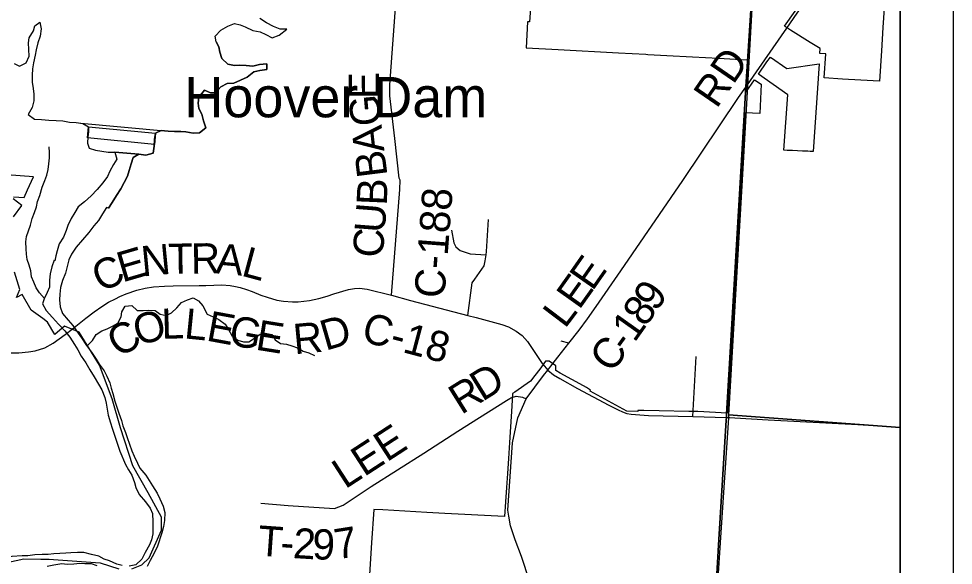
# Model space of a CAD drawing. Extents: x 0 to 34, y 0 to 22.
# Drawn here: x 7.246 to 9, y 18.938 to 19.964 of the extents above; entities that cross this region are included whole.
import ezdxf

# ---------------------------------------------------------------- set-up
doc = ezdxf.new("R2010")
doc.units = 0
for name, color, linetype in [('Default', 7, 'Continuous'), ('GM_X_Corporation', 7, 'Continuous'), ('GM_X_County_Road', 7, 'Continuous'), ('GM_X_County_Road_Text', 7, 'Continuous'), ('GM_X_Hydro', 7, 'Continuous'), ('GM_X_Hydro_Text', 7, 'Continuous'), ('GM_X_Major_Lake', 7, 'Continuous'), ('GM_X_Major_River', 7, 'Continuous'), ('GM_X_Minor_River', 7, 'Continuous'), ('GM_X_Township_Road', 7, 'Continuous'), ('GM_X_Township_Road_Text', 7, 'Continuous'), ('SH_Data', 7, 'Continuous')]:
    doc.layers.add(name, color=color, linetype=linetype)

msp = doc.modelspace()

# ---------------------------------------------------------------- linework, layer by layer
at = {"layer": 'Default'}
for points in [[(8.9, 19.1966), (8.9, 20.2132), (8.6374, 20.2329), (8.6338, 20.179), (8.6233, 20.0051), (8.6057, 19.6933), (8.5782, 19.2201)], [(8.9, 18.6616), (8.9, 19.1966), (8.5782, 19.2201), (8.5779, 19.2144), (8.5637, 18.9993), (8.5431, 18.6841)]]:
    msp.add_lwpolyline(points, close=True, dxfattribs=at)
at = {"layer": 'GM_X_Corporation'}
for points in [[(8.9, 16.0691), (8.9, 20.2026)], [(8.2101, 20.0366), (8.2048, 19.9577), (8.2009, 19.9579), (8.1985, 19.9091), (8.2581, 19.9059), (8.3717, 19.8996), (8.423, 19.8968), (8.4268, 19.8966), (8.4622, 19.8946), (8.5104, 19.892), (8.5591, 19.8893), (8.6016, 19.8869), (8.6149, 19.8862), (8.6149, 19.8862), (8.6149, 19.8862), (8.6126, 19.8519), (8.6124, 19.8478), (8.6114, 19.8265), (8.6271, 19.8492), (8.6394, 19.8405), (8.6369, 19.786), (8.6093, 19.787), (8.607, 19.7425), (8.6058, 19.7195), (8.6055, 19.7139), (8.6047, 19.7018), (8.6042, 19.6931), (8.6031, 19.6746), (8.6026, 19.6668), (8.6022, 19.6605), (8.6017, 19.651), (8.6011, 19.642), (8.6005, 19.6321), (8.5999, 19.6227), (8.5994, 19.6132), (8.5987, 19.6028), (8.5981, 19.593), (8.5976, 19.5835), (8.5968, 19.571), (8.5959, 19.5552), (8.5954, 19.548), (8.5946, 19.5342), (8.5944, 19.5318), (8.594, 19.5248), (8.5934, 19.5153), (8.5929, 19.5059), (8.5923, 19.4964), (8.5917, 19.487), (8.5911, 19.4775), (8.5906, 19.4679), (8.59, 19.4586), (8.5894, 19.4492), (8.5888, 19.4386), (8.5881, 19.428), (8.5872, 19.4125), (8.5868, 19.406), (8.5858, 19.3894), (8.5852, 19.38), (8.5846, 19.3701), (8.5841, 19.3607), (8.5835, 19.3512), (8.5829, 19.3408), (8.5823, 19.3319), (8.5817, 19.3225), (8.5811, 19.3127), (8.5806, 19.3032), (8.58, 19.2934), (8.5794, 19.2839), (8.5792, 19.2811), (8.5788, 19.2741), (8.5782, 19.2646), (8.5775, 19.2526), (8.5759, 19.2262), (8.5758, 19.2236), (8.5203, 19.2263), (8.5035, 19.2266), (8.4477, 19.2277), (8.4193, 19.2283), (8.4079, 19.2285), (8.4078, 19.2268), (8.3875, 19.2271), (8.3183, 19.2647), (8.3192, 19.2663), (8.3113, 19.2717), (8.306, 19.2745), (8.2623, 19.2982), (8.2541, 19.3033), (8.2542, 19.3125), (8.2412, 19.3208), (8.2347, 19.3207), (8.2241, 19.3061), (8.2147, 19.2942), (8.2064, 19.2836), (8.1769, 19.2631), (8.1723, 19.26), (8.1716, 19.2365), (8.1691, 19.198), (8.1671, 19.1683), (8.1651, 19.1386), (8.1633, 19.1102), (8.1615, 19.0836), (8.1597, 19.0568), (8.1579, 19.0296), (8.0457, 19.0349), (8.0118, 19.0369), (7.9291, 19.0419), (7.9121, 19.0429), (7.908, 18.98), (7.9029, 18.9004)], [(8.8726, 20.0212), (8.8678, 19.9474), (8.865, 19.9032), (8.8613, 19.8462), (8.8267, 19.8483), (8.7921, 19.8504), (8.7577, 19.8525), (8.7605, 19.8979), (8.7496, 19.8985), (8.7502, 19.9075), (8.7315, 19.9191), (8.6942, 19.9423), (8.6926, 19.9434), (8.683, 19.9494), (8.7229, 20.0068)], [(7.2358, 19.6296), (7.2557, 19.6283), (7.2624, 19.6426), (7.2737, 19.6668), (7.1807, 19.674)], [(7.2359, 19.5917), (7.2516, 19.6128), (7.2356, 19.6258)], [(7.4582, 18.9315), (7.4768, 18.9386), (7.4904, 18.952), (7.514, 19.0041), (7.5139, 19.0283), (7.4886, 19.0736), (7.4602, 19.1244), (7.437, 19.1957), (7.4213, 19.2503), (7.3975, 19.3136), (7.3591, 19.3754), (7.3315, 19.3868), (7.3137, 19.3711), (7.2996, 19.3944), (7.2912, 19.4013), (7.2689, 19.4166), (7.2521, 19.4458), (7.2416, 19.4406), (7.248, 19.4555), (7.238, 19.4882)], [(7.1741, 18.9115), (7.2181, 18.9421), (7.2552, 18.9501), (7.2874, 18.9493), (7.2953, 18.9495), (7.3032, 18.9493), (7.3111, 18.9486), (7.3984, 18.9427), (7.4334, 18.9313)]]:
    msp.add_lwpolyline(points, dxfattribs=at)
msp.add_lwpolyline([(8.7074, 19.7156), (8.6979, 19.716), (8.6884, 19.7163), (8.6822, 19.7166), (8.6891, 19.8208), (8.6344, 19.8597), (8.6503, 19.8825), (8.6567, 19.8917), (8.6874, 19.8703), (8.7484, 19.8791), (8.737, 19.7145), (8.7315, 19.7147), (8.7267, 19.7149), (8.7168, 19.7153)], close=True, dxfattribs=at)
at = {"layer": 'GM_X_County_Road'}
for p, q in [((8.6305, 19.8639), (8.6874, 19.9459)), ((8.6134, 19.8393), (8.6305, 19.8639)), ((8.2324, 19.3115), (8.2388, 19.3039)), ((8.2388, 19.3039), (8.2445, 19.3113))]:
    msp.add_line(p, q, dxfattribs=at)
for points in [[(8.4511, 17.1951), (8.4574, 17.2984), (8.4834, 17.726), (8.4924, 17.8634), (8.4933, 17.8764), (8.5463, 18.6832), (8.5517, 18.8459), (8.5602, 18.986), (8.5739, 19.2101), (8.5742, 19.2159), (8.5745, 19.2215), (8.6104, 19.8358), (8.636, 20.2294), (8.6772, 20.9), (3.9336, 20.9)], [(7.9453, 19.445), (7.9609, 19.6428), (7.9617, 19.6607), (7.9601, 19.6645), (7.9516, 19.7386), (7.9426, 19.8187), (7.9422, 19.8278), (7.9426, 19.8396), (7.9547, 20.0094), (7.9614, 20.1033), (7.9665, 20.1933), (7.9716, 20.2761), (7.9801, 20.3643), (7.9832, 20.4168)], [(8.6874, 19.9459), (8.7068, 19.9738), (8.7395, 20.0202), (8.7885, 20.0901), (8.8301, 20.1469), (8.8468, 20.1682), (8.8566, 20.1827), (8.8626, 20.203), (8.8633, 20.2102)], [(8.2445, 19.3113), (8.2576, 19.3282), (8.2782, 19.3547), (8.2977, 19.3793), (8.3136, 19.4005), (8.3296, 19.4234), (8.3762, 19.4905), (8.4924, 19.6602), (8.5968, 19.8155), (8.6106, 19.8352), (8.6134, 19.8393)], [(7.3532, 19.3866), (7.372, 19.4015), (7.3875, 19.4133), (7.4017, 19.4233), (7.4144, 19.4314), (7.4274, 19.4382), (7.4358, 19.4424), (7.4473, 19.4472), (7.4672, 19.4542), (7.4831, 19.458), (7.499, 19.4607), (7.5196, 19.4619), (7.5359, 19.4625), (7.5842, 19.4631)], [(7.5842, 19.4631), (7.5973, 19.4632), (7.6273, 19.464), (7.6424, 19.4629), (7.6528, 19.4613), (7.6617, 19.459), (7.6736, 19.4555), (7.6842, 19.4516), (7.7005, 19.4451), (7.7119, 19.4408), (7.73, 19.4355), (7.7429, 19.4335), (7.7596, 19.4323), (7.7706, 19.4322), (7.781, 19.4334), (7.7914, 19.4349), (7.8093, 19.4386), (7.8245, 19.4432), (7.8373, 19.4474), (7.8645, 19.4552), (7.8759, 19.4571), (7.8853, 19.4577), (7.9001, 19.4562), (7.9453, 19.445), (7.9813, 19.4346), (8.0886, 19.4067), (8.1043, 19.4027), (8.1526, 19.3897), (8.1653, 19.3851), (8.1797, 19.3774), (8.1907, 19.3691), (8.2009, 19.3576), (8.228, 19.3168), (8.2324, 19.3115)], [(7.0874, 19.347), (7.1621, 19.3409), (7.2264, 19.3363), (7.2457, 19.3363), (7.2644, 19.3382), (7.2765, 19.3403), (7.2946, 19.3457), (7.3106, 19.3545), (7.3332, 19.3707), (7.3462, 19.381), (7.3532, 19.3866)], [(8.1656, 19.03), (8.1636, 19.0412), (8.1727, 19.1677), (8.1825, 19.2149), (8.1981, 19.2503), (8.2308, 19.2941), (8.2388, 19.3039)], [(8.2388, 19.3039), (8.2498, 19.2952), (8.2614, 19.2882), (8.2949, 19.2697), (8.3532, 19.2383), (8.3711, 19.2297), (8.3791, 19.226), (8.3872, 19.2228), (8.3952, 19.2212), (8.4276, 19.2187), (8.5112, 19.2172), (8.5744, 19.2154), (8.5806, 19.2151)], [(8.5806, 19.2151), (8.5899, 19.2146), (8.6527, 19.2111), (8.8207, 19.2019), (8.9, 19.1974)], [(8.251, 18.3328), (8.267, 18.5617), (8.2747, 18.6747), (8.2755, 18.6956), (8.2751, 18.6998), (8.2717, 18.7125), (8.2411, 18.7994), (8.2194, 18.8631), (8.1895, 18.9547), (8.1777, 18.9855), (8.1688, 19.0118), (8.1656, 19.03)]]:
    msp.add_lwpolyline(points, dxfattribs=at)
msp.add_lwpolyline([(8.9, 16.069), (8.9, 20.9), (8.6772, 20.9), (8.636, 20.2294), (8.6104, 19.8358), (8.5745, 19.2215), (8.5742, 19.2159), (8.5739, 19.2101), (8.5602, 18.986), (8.5517, 18.8459), (8.5463, 18.6832), (8.4933, 17.8764), (8.4924, 17.8634), (8.4834, 17.726), (8.4574, 17.2984), (8.4511, 17.1951), (8.4246, 16.7343), (8.4151, 16.5575), (8.4046, 16.4383), (8.3992, 16.2979), (8.3884, 16.1033), (8.4715, 16.0965), (8.5217, 16.0919)], close=True, dxfattribs=at)
at = {"layer": 'GM_X_Hydro'}
msp.add_lwpolyline([(7.3749, 19.7402), (7.3769, 19.7609), (7.5028, 19.7486), (7.5008, 19.7278)], close=True, dxfattribs=at)
at = {"layer": 'GM_X_Major_Lake'}
for p, q in [((7.3621, 19.7673), (7.5193, 19.7531)), ((7.426, 19.7132), (7.4715, 19.7092))]:
    msp.add_line(p, q, dxfattribs=at)
for points in [[(7.6167, 19.9204), (7.6148, 19.931), (7.6251, 19.942), (7.6381, 19.9499), (7.651, 19.9544), (7.6612, 19.9521), (7.6711, 19.9483), (7.6851, 19.9417), (7.6987, 19.939), (7.7093, 19.9337), (7.7214, 19.9279), (7.7347, 19.9324), (7.7488, 19.9437), (7.7363, 19.9442), (7.7238, 19.9488), (7.7109, 19.9557), (7.6985, 19.9637)], [(7.2474, 19.8743), (7.2599, 19.8807), (7.2653, 19.8935), (7.2646, 19.9057), (7.2643, 19.9182), (7.2655, 19.9277), (7.2735, 19.941), (7.2762, 19.9504), (7.2857, 19.9569), (7.2879, 19.9447), (7.286, 19.9307), (7.2814, 19.9185), (7.2786, 19.9049), (7.2767, 19.895), (7.2736, 19.8806), (7.2716, 19.8696), (7.2708, 19.8578), (7.2708, 19.8442), (7.273, 19.8324), (7.2744, 19.8218), (7.2744, 19.8096), (7.2713, 19.7967), (7.2636, 19.7838), (7.2757, 19.775), (7.2886, 19.7742), (7.3023, 19.773), (7.3159, 19.7726), (7.3288, 19.7718), (7.341, 19.7694), (7.3538, 19.7686), (7.3621, 19.7673)], [(7.2474, 19.8743), (7.2599, 19.8807), (7.2653, 19.8935), (7.2646, 19.9057), (7.2643, 19.9182), (7.2655, 19.9277), (7.2735, 19.941), (7.2762, 19.9504), (7.2857, 19.9569), (7.2879, 19.9447), (7.286, 19.9307), (7.2814, 19.9185), (7.2786, 19.9049), (7.2767, 19.895), (7.2736, 19.8806), (7.2716, 19.8696), (7.2708, 19.8578), (7.2708, 19.8442), (7.273, 19.8324), (7.2744, 19.8218), (7.2744, 19.8096), (7.2713, 19.7967), (7.2636, 19.7838), (7.2757, 19.775), (7.2886, 19.7742), (7.3023, 19.773), (7.3159, 19.7726), (7.3288, 19.7718), (7.341, 19.7694), (7.3538, 19.7686), (7.3663, 19.7667), (7.3769, 19.7609), (7.3765, 19.7514), (7.3757, 19.7419), (7.3749, 19.7302), (7.3783, 19.7207), (7.39, 19.7172), (7.4018, 19.7149), (7.4139, 19.7133), (7.426, 19.7132)], [(7.2474, 19.8743), (7.2599, 19.8807), (7.2653, 19.8935), (7.2646, 19.9057), (7.2643, 19.9182), (7.2655, 19.9277), (7.2735, 19.941), (7.2762, 19.9504), (7.2857, 19.9569), (7.2879, 19.9447), (7.286, 19.9307), (7.2814, 19.9185), (7.2786, 19.9049), (7.2767, 19.895), (7.2736, 19.8806), (7.2716, 19.8696), (7.2708, 19.8578), (7.2708, 19.8442), (7.273, 19.8324), (7.2744, 19.8218), (7.2744, 19.8096), (7.2713, 19.7967), (7.2636, 19.7838), (7.2757, 19.775), (7.2886, 19.7742), (7.3023, 19.773), (7.3159, 19.7726), (7.3288, 19.7718), (7.341, 19.7694), (7.3538, 19.7686), (7.3663, 19.7667), (7.3769, 19.7609), (7.3765, 19.7514), (7.3757, 19.7419), (7.3749, 19.7302), (7.3783, 19.7207), (7.39, 19.7172), (7.4018, 19.7149), (7.4139, 19.7133), (7.426, 19.7132)], [(7.4715, 19.7092), (7.4844, 19.7073), (7.4981, 19.7114), (7.5, 19.7247), (7.5005, 19.7372), (7.5028, 19.7486), (7.5131, 19.7538), (7.5263, 19.7523), (7.5381, 19.7518), (7.5499, 19.7518), (7.5597, 19.751), (7.573, 19.749), (7.5851, 19.7493), (7.5973, 19.7588), (7.5924, 19.7721), (7.5895, 19.7846), (7.5838, 19.7953), (7.5827, 19.8048), (7.5839, 19.8162), (7.5942, 19.8298), (7.6056, 19.8244), (7.6151, 19.8244), (7.6254, 19.8357), (7.6368, 19.8421), (7.6493, 19.8424), (7.6622, 19.8481), (7.6744, 19.8541), (7.687, 19.8639), (7.6984, 19.8661), (7.7116, 19.8683), (7.7113, 19.879), (7.698, 19.8779), (7.6855, 19.8745), (7.673, 19.8757), (7.6605, 19.8765), (7.6506, 19.8758), (7.6385, 19.8782), (7.6268, 19.8889), (7.6234, 19.901), (7.6212, 19.9109), (7.6167, 19.9204)], [(7.6167, 19.9204), (7.6212, 19.9109), (7.6234, 19.901), (7.6268, 19.8889), (7.6385, 19.8782), (7.6506, 19.8758), (7.6605, 19.8765), (7.673, 19.8757), (7.6855, 19.8745), (7.698, 19.8779), (7.7113, 19.879), (7.7116, 19.8683), (7.6984, 19.8661), (7.687, 19.8639), (7.6744, 19.8541), (7.6622, 19.8481), (7.6493, 19.8424), (7.6368, 19.8421), (7.6254, 19.8357), (7.6151, 19.8244), (7.6056, 19.8244), (7.5942, 19.8298), (7.5839, 19.8162), (7.5827, 19.8048), (7.5838, 19.7953), (7.5895, 19.7846), (7.5924, 19.7721), (7.5973, 19.7588), (7.5851, 19.7493), (7.573, 19.749), (7.5597, 19.751), (7.5499, 19.7518), (7.5381, 19.7518), (7.5263, 19.7523), (7.5131, 19.7538), (7.5028, 19.7486), (7.5005, 19.7372), (7.5, 19.7247), (7.4981, 19.7114), (7.4844, 19.7073), (7.4715, 19.7092)], [(7.5193, 19.7531), (7.5263, 19.7523), (7.5381, 19.7518), (7.5499, 19.7518), (7.5597, 19.751), (7.573, 19.749), (7.5851, 19.7493), (7.5973, 19.7588), (7.5924, 19.7721), (7.5895, 19.7846), (7.5838, 19.7953), (7.5827, 19.8048), (7.5839, 19.8162), (7.5942, 19.8298), (7.6056, 19.8244), (7.6151, 19.8244), (7.6254, 19.8357), (7.6368, 19.8421), (7.6493, 19.8424), (7.6622, 19.8481), (7.6744, 19.8541), (7.687, 19.8639), (7.6984, 19.8661), (7.7116, 19.8683), (7.7113, 19.879), (7.698, 19.8779), (7.6855, 19.8745), (7.673, 19.8757), (7.6605, 19.8765), (7.6506, 19.8758), (7.6385, 19.8782), (7.6268, 19.8889), (7.6234, 19.901), (7.6212, 19.9109), (7.6167, 19.9204)], [(7.2372, 19.8796), (7.2474, 19.8743)]]:
    msp.add_lwpolyline(points, dxfattribs=at)
at = {"layer": 'GM_X_Major_River'}
msp.add_line((7.4715, 19.7092), (7.426, 19.7132), dxfattribs=at)
for points in [[(7.426, 19.7132), (7.4297, 19.6999), (7.4236, 19.6897), (7.4167, 19.6776), (7.4125, 19.6677), (7.4037, 19.6553), (7.3931, 19.6432), (7.3816, 19.6311), (7.3694, 19.6197), (7.3576, 19.6103), (7.3511, 19.6001), (7.3442, 19.5887), (7.3381, 19.5755), (7.335, 19.566), (7.3297, 19.5539), (7.3216, 19.541), (7.3178, 19.5281), (7.3154, 19.5186), (7.3135, 19.5091)], [(7.426, 19.7132), (7.4297, 19.6999), (7.4236, 19.6897), (7.4167, 19.6776), (7.4125, 19.6677), (7.4037, 19.6553), (7.3931, 19.6432), (7.3816, 19.6311), (7.3694, 19.6197), (7.3576, 19.6103), (7.3511, 19.6001), (7.3442, 19.5887), (7.3381, 19.5755), (7.335, 19.566), (7.3297, 19.5539), (7.3216, 19.541), (7.3178, 19.5281), (7.3154, 19.5186), (7.3135, 19.5091)], [(7.4145, 19.6081), (7.4214, 19.6187), (7.4294, 19.632), (7.4374, 19.6441), (7.444, 19.6562), (7.4497, 19.668), (7.4532, 19.6789), (7.457, 19.6915), (7.4605, 19.7032), (7.4715, 19.7092)], [(7.4715, 19.7092), (7.4605, 19.7032), (7.457, 19.6915), (7.4532, 19.6789), (7.4497, 19.668), (7.444, 19.6562), (7.4374, 19.6441), (7.4294, 19.632), (7.4214, 19.6187), (7.4145, 19.6081)], [(7.4145, 19.6081), (7.4103, 19.6093), (7.4031, 19.5972), (7.3954, 19.5847), (7.3867, 19.5748), (7.3771, 19.5624), (7.3653, 19.5487), (7.3535, 19.5348), (7.3447, 19.5215), (7.3397, 19.5113), (7.337, 19.4988), (7.3335, 19.4859), (7.3281, 19.4726), (7.3239, 19.4593), (7.3227, 19.4464), (7.3223, 19.4358), (7.3233, 19.4229), (7.3282, 19.4104), (7.3388, 19.3982), (7.3474, 19.3882), (7.3542, 19.378), (7.3636, 19.365), (7.373, 19.3502), (7.3825, 19.338), (7.3911, 19.3246), (7.3968, 19.3151), (7.4062, 19.3026), (7.4111, 19.293), (7.4167, 19.2801), (7.4193, 19.2706), (7.4223, 19.2603), (7.4264, 19.2459), (7.4339, 19.2231), (7.4387, 19.2094), (7.4413, 19.1995), (7.4462, 19.1873), (7.4492, 19.1778), (7.4537, 19.1649), (7.4578, 19.1527), (7.4627, 19.1428), (7.4687, 19.1295), (7.4732, 19.12), (7.4841, 19.1071), (7.4909, 19.0972), (7.4969, 19.0873), (7.5056, 19.0735), (7.5108, 19.0629), (7.5168, 19.0488), (7.5202, 19.037), (7.5194, 19.0219), (7.5174, 19.0109), (7.5147, 18.9987), (7.5062, 18.9737), (7.5001, 18.9604), (7.4928, 18.9468), (7.4871, 18.9354)], [(7.3135, 19.5091), (7.3124, 19.5106), (7.3078, 19.4978), (7.305, 19.4849), (7.3035, 19.4727), (7.3034, 19.4598), (7.2992, 19.45), (7.2938, 19.4378), (7.2907, 19.4284), (7.2971, 19.4158), (7.3092, 19.4028), (7.3205, 19.3906), (7.3326, 19.3781), (7.342, 19.3659), (7.3503, 19.3525), (7.3567, 19.3423), (7.3631, 19.3305), (7.3717, 19.3179), (7.3793, 19.3046), (7.3875, 19.2916), (7.3954, 19.2775), (7.4015, 19.2669), (7.4075, 19.2528), (7.4097, 19.2422), (7.4119, 19.2308), (7.4137, 19.2198), (7.4182, 19.2053), (7.4212, 19.1954), (7.425, 19.184), (7.4283, 19.1745), (7.4317, 19.1635), (7.4354, 19.1521), (7.4459, 19.127), (7.4519, 19.1171), (7.4583, 19.1068), (7.4632, 19.0931), (7.4654, 19.0836), (7.4718, 19.071), (7.4839, 19.0573), (7.4926, 19.0451), (7.4967, 19.0349), (7.4974, 19.0197), (7.4972, 18.9969), (7.4953, 18.9855), (7.4915, 18.976), (7.4834, 18.9617), (7.4769, 18.9492), (7.4655, 18.939), (7.4533, 18.9364)], [(7.4401, 18.9376), (7.4302, 18.9399), (7.4162, 18.946), (7.4064, 18.9491), (7.3961, 18.9552), (7.3825, 18.9583), (7.3681, 18.9618), (7.3564, 18.9622), (7.3434, 18.9612), (7.334, 18.9604), (7.323, 18.9601), (7.3116, 18.9594), (7.3013, 18.9583), (7.29, 18.958), (7.2759, 18.9573), (7.2626, 18.9555), (7.2524, 18.9555), (7.2327, 18.9541), (7.2209, 18.9515), (7.2083, 18.9466), (7.1946, 18.936)], [(7.393, 18.9366), (7.3824, 18.9405), (7.3699, 18.9405), (7.3604, 18.941), (7.349, 18.9399), (7.3365, 18.9392), (7.327, 18.9404), (7.3119, 18.9381), (7.2989, 18.9359)]]:
    msp.add_lwpolyline(points, dxfattribs=at)
at = {"layer": 'GM_X_Minor_River'}
for points in [[(7.2942, 19.4388), (7.2848, 19.449), (7.2785, 19.4586), (7.2744, 19.4692), (7.2695, 19.4792), (7.2685, 19.4902), (7.2652, 19.5008), (7.2619, 19.5119), (7.2604, 19.5218), (7.2598, 19.5317), (7.2591, 19.5446), (7.2604, 19.5548), (7.2639, 19.5658), (7.2678, 19.576), (7.2713, 19.5885), (7.2752, 19.5999), (7.2791, 19.6105), (7.2811, 19.6207), (7.2857, 19.6317), (7.29, 19.6476), (7.2947, 19.6597), (7.2986, 19.6703), (7.3013, 19.6809), (7.3025, 19.6915), (7.3038, 19.7025), (7.3035, 19.7131), (7.3032, 19.7226), (7.3032, 19.7234)], [(7.3738, 19.3491), (7.3841, 19.3596), (7.391, 19.3709), (7.402, 19.3781), (7.4116, 19.3818), (7.4218, 19.3866), (7.4321, 19.3922), (7.4383, 19.4043), (7.4391, 19.4138), (7.4453, 19.4244), (7.4582, 19.4254), (7.468, 19.4162), (7.4793, 19.4161), (7.4899, 19.4167), (7.5017, 19.4162), (7.5115, 19.4089), (7.5224, 19.4066), (7.5323, 19.4118), (7.5427, 19.4212), (7.5515, 19.431), (7.5625, 19.4362), (7.5732, 19.4399), (7.583, 19.4341), (7.5916, 19.4245), (7.5994, 19.4089), (7.6107, 19.4042), (7.6213, 19.3992), (7.6334, 19.3903), (7.6397, 19.3804), (7.6457, 19.3689), (7.6573, 19.3605), (7.6675, 19.3574), (7.6774, 19.3573), (7.6885, 19.364), (7.6991, 19.3715), (7.7086, 19.3737), (7.7211, 19.3709), (7.7271, 19.361), (7.7373, 19.354), (7.7486, 19.3528), (7.7584, 19.35), (7.769, 19.3462), (7.7796, 19.34), (7.7902, 19.3365), (7.8011, 19.3314)]]:
    msp.add_lwpolyline(points, dxfattribs=at)
at = {"layer": 'GM_X_Township_Road'}
for p, q in [((8.2782, 19.3547), (8.2637, 19.3586)), ((8.5112, 19.2172), (8.5175, 19.33)), ((8.1105, 19.215), (8.1611, 19.2469))]:
    msp.add_line(p, q, dxfattribs=at)
for points in [[(8.0886, 19.4067), (8.0968, 19.468), (8.1017, 19.4749), (8.1195, 19.4996), (8.121, 19.5091), (8.123, 19.5203), (8.124, 19.5266), (8.1277, 19.587)], [(8.0581, 19.5667), (8.0628, 19.5428), (8.0662, 19.5356), (8.0746, 19.5284), (8.0929, 19.5224), (8.123, 19.5203)], [(8.1611, 19.2469), (8.1678, 19.2512), (8.1697, 19.2519)], [(8.1697, 19.2519), (8.1793, 19.2553), (8.1913, 19.2536), (8.1981, 19.2503)], [(7.7001, 19.0542), (7.7515, 19.0504), (7.8385, 19.0445), (7.8546, 19.0509), (7.9071, 19.086), (8.0063, 19.1486), (8.07, 19.1894), (8.1105, 19.215)]]:
    msp.add_lwpolyline(points, dxfattribs=at)
at = {"layer": 'SH_Data'}
for p, q in [((9, 21), (9, 14)), ((8.9, 20.9), (8.9, 14.1))]:
    msp.add_line(p, q, dxfattribs=at)

# ---------------------------------------------------------------- texts
at = {"layer": 'GM_X_County_Road_Text'}
for s, height, rotation, p in [('RD', 0.05682, 55.4889, (8.5558, 19.7933)), ('E', 0.0568, 90.3086, (7.9222, 19.8132)), ('G', 0.0568, 95.3372, (7.9268, 19.7648)), ('A', 0.0568, 96.3845, (7.9323, 19.7154)), ('B', 0.0568, 97.1304, (7.9381, 19.6692)), ('B', 0.0568, 87.5333, (7.9365, 19.6123)), ('C-188', 0.05682, 85.6016, (8.0447, 19.4379)), ('U', 0.0568, 85.6421, (7.9325, 19.5604)), ('C', 0.0568, 85.6282, (7.929, 19.5138)), ('R', 0.0568, 0.804, (7.5693, 19.4852)), ('E', 0.0568, 16.2851, (7.4402, 19.4684)), ('N', 0.0568, 5.4543, (7.4782, 19.4798)), ('T', 0.0568, 1.0372, (7.5268, 19.4845)), ('A', 0.0568, 354.7838, (7.6144, 19.4859)), ('L', 0.0568, 344.9565, (7.6616, 19.4819)), ('C', 0.0568, 25.5526, (7.4004, 19.4491)), ('E', 0.0568, 55.0342, (8.3226, 19.4509)), ('E', 0.0568, 54.5442, (8.2977, 19.4158)), ('9', 0.0568, 55.1987, (8.4421, 19.4121)), ('8', 0.0568, 55.09, (8.422, 19.3833)), ('L', 0.0568, 1.6073, (7.5145, 19.3627)), ('L', 0.0568, 354.338, (7.5551, 19.3639)), ('L', 0.0568, 52.8704, (8.271, 19.3805)), ('O', 0.0568, 16.1996, (7.4703, 19.3493)), ('E', 0.0568, 349.6457, (7.5962, 19.3599)), ('G', 0.0568, 349.3788, (7.6379, 19.3523)), ('D', 0.0568, 16.1257, (7.8216, 19.3403)), ('C-18', 0.05682, 345.1267, (7.8867, 19.3589)), ('1', 0.0568, 54.661, (8.4015, 19.3544)), ('C', 0.0568, 32.6628, (7.4349, 19.3259)), ('E', 0.0568, 350.9264, (7.6887, 19.3428)), ('R', 0.0568, 5.2678, (7.7636, 19.3338)), ('-', 0.0568, 54.2034, (8.3876, 19.335)), ('C', 0.0568, 52.8569, (8.3585, 19.2966))]:
    msp.add_text(s, height=height, rotation=rotation, dxfattribs=at).set_placement(p)
at = {"layer": 'GM_X_Hydro_Text'}
msp.add_text('Hoover Dam', height=0.07576, rotation=0.0053, dxfattribs=at).set_placement((7.5567, 19.7786))
at = {"layer": 'GM_X_Township_Road_Text'}
for s, height, rotation, p in [('D', 0.0568, 31.7803, (8.116, 19.2443)), ('R', 0.0568, 32.0087, (8.0765, 19.2196)), ('LEE', 0.05682, 32.9625, (7.8585, 19.0801)), ('T', 0.0568, 355.8951, (7.6933, 18.9563)), ('2', 0.0568, 356.4211, (7.7595, 18.9516)), ('9', 0.0568, 358.1625, (7.7963, 18.9493)), ('7', 0.0568, 8.9398, (7.8429, 18.9489)), ('-', 0.0568, 355.9984, (7.7358, 18.9533))]:
    msp.add_text(s, height=height, rotation=rotation, dxfattribs=at).set_placement(p)

doc.saveas('drawing.dxf')
